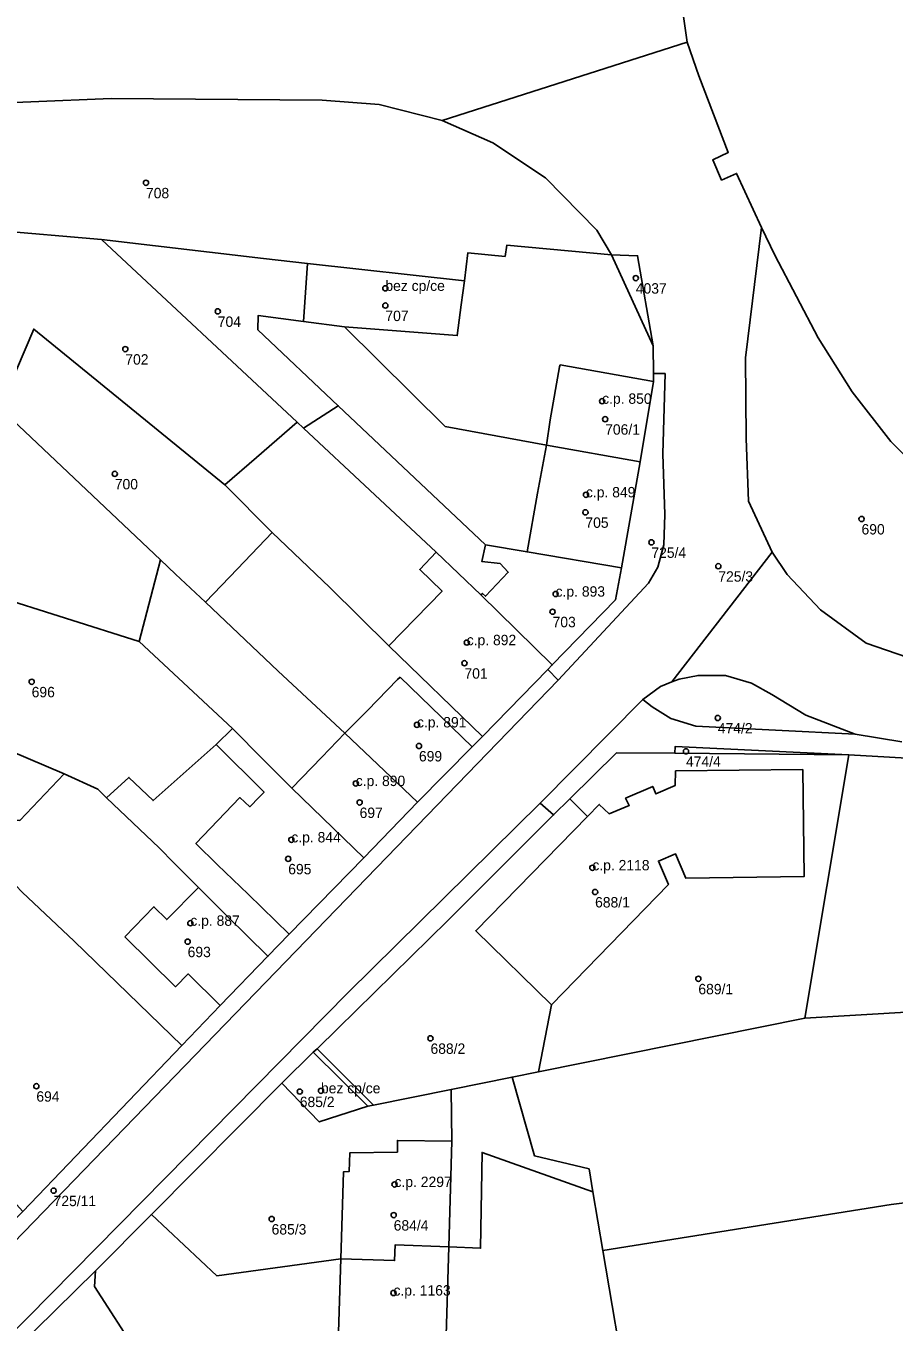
# Model space of a CAD drawing. Extents: x -878211 to -870363, y -1058464 to -1052522.
# Drawn here: x -874627.3 to -874543.8, y -1056425.6 to -1056300.9 of the extents above; entities that cross this region are included whole.
import ezdxf

# ---------------------------------------------------------------- set-up
doc = ezdxf.new("R2010")
doc.units = 0
for name, color, linetype in [('Definiční body', 7, 'Continuous'), ('Polygon budovy', 7, 'Continuous'), ('Polygon parcely', 7, 'Continuous')]:
    doc.layers.add(name, color=color, linetype=linetype)

msp = doc.modelspace()

# ---------------------------------------------------------------- linework, layer by layer
at = {"layer": 'Definiční body'}
for centre in [(-874615.77, -1056315.99994), (-874568.63, -1056325.16994), (-874592.73, -1056326.14994), (-874592.73, -1056327.80994), (-874608.86, -1056328.36994), (-874617.76, -1056331.99994), (-874571.87, -1056337.00994), (-874571.58, -1056338.73994), (-874618.77, -1056343.99994), (-874573.43, -1056346.00994), (-874573.48, -1056347.69994), (-874546.91, -1056348.33994), (-874567.13, -1056350.58994), (-874560.69, -1056352.87994), (-874576.35, -1056355.55994), (-874576.64, -1056357.25994), (-874584.9, -1056360.22994), (-874585.12, -1056362.20994), (-874626.77, -1056363.99994), (-874560.74, -1056367.47994), (-874589.69, -1056368.13994), (-874589.5, -1056370.16994), (-874563.8, -1056370.68994), (-874595.58, -1056373.77994), (-874595.21, -1056375.60994), (-874601.78, -1056379.19994), (-874602.08, -1056381.02994), (-874572.81, -1056381.88994), (-874572.55, -1056384.21994), (-874611.5, -1056387.21994), (-874611.76, -1056388.99994), (-874562.61, -1056392.56994), (-874588.39, -1056398.29994), (-874626.32, -1056402.89994), (-874600.97, -1056403.41994), (-874598.93, -1056403.33994), (-874591.85, -1056412.34994), (-874624.66, -1056412.94994), (-874603.68, -1056415.67994), (-874591.93, -1056415.29994), (-874591.95, -1056422.78994)]:
    msp.add_circle(centre, 0.25, dxfattribs=at)
at = {"layer": 'Polygon budovy'}
for points in [[(-874600.61, -1056329.35), (-874596.68, -1056329.87), (-874585.82, -1056330.7), (-874585.43, -1056327.73), (-874585.13, -1056325.44), (-874600.21, -1056323.77)], [(-874575.92, -1056333.5), (-874575.96, -1056333.7), (-874576.86, -1056338.81), (-874577.23, -1056341.24), (-874568.21, -1056342.85), (-874566.92, -1056335.1)], [(-874578.08, -1056345.85), (-874579.09, -1056351.51), (-874570.02, -1056353.03), (-874568.21, -1056342.85), (-874577.23, -1056341.24)], [(-874570.57, -1056356.1), (-874570.02, -1056353.03), (-874579.09, -1056351.51), (-874583.1, -1056350.84), (-874583.44, -1056352.43), (-874581.7, -1056352.63), (-874580.91, -1056353.47), (-874583.11, -1056355.77), (-874583.39, -1056355.5), (-874583.54, -1056355.64), (-874576.68, -1056362.38)], [(-874592.39, -1056360.55), (-874583.39, -1056369.26), (-874577.11, -1056362.82), (-874576.68, -1056362.38), (-874583.54, -1056355.64), (-874587.83, -1056351.54), (-874589.42, -1056353.2), (-874587.27, -1056355.27)], [(-874591.31, -1056363.55), (-874591.55, -1056363.78), (-874594.44, -1056366.75), (-874596.63, -1056368.95), (-874589.63, -1056375.57), (-874584.38, -1056370.26)], [(-874594.8, -1056380.92), (-874601.73, -1056374.23), (-874604.5, -1056371.46), (-874607.45, -1056368.5), (-874609, -1056370.04), (-874604.4, -1056374.61), (-874604.88, -1056375.11), (-874605.78, -1056376.02), (-874606.75, -1056375.14), (-874610.97, -1056379.54), (-874608.9, -1056381.6), (-874605.92, -1056384.44), (-874601.99, -1056388.27)], [(-874598.85, -1056371.26), (-874601.73, -1056374.23), (-874594.8, -1056380.92), (-874589.63, -1056375.57), (-874596.63, -1056368.95)], [(-874584.04, -1056387.95), (-874576.73, -1056395.06), (-874565.49, -1056383.5), (-874566.45, -1056381.25), (-874564.81, -1056380.56), (-874563.82, -1056382.88), (-874552.43, -1056382.73), (-874552.56, -1056372.44), (-874564.81, -1056372.58), (-874564.83, -1056373.96), (-874566.7, -1056374.79), (-874567, -1056374.06), (-874569.62, -1056375.2), (-874569.27, -1056375.89), (-874571.18, -1056376.7), (-874572.15, -1056375.8), (-874573.28, -1056376.95)], [(-874617.8, -1056388.54), (-874612.93, -1056393.33), (-874611.71, -1056392.1), (-874608.63, -1056395.13), (-874604.04, -1056390.4), (-874607.99, -1056386.5), (-874610.71, -1056383.8), (-874613.77, -1056386.88), (-874615.01, -1056385.64)], [(-874602.69, -1056402.62), (-874599.09, -1056406.34), (-874594.43, -1056404.83), (-874599.67, -1056399.64)], [(-874596.75, -1056411.13), (-874597.02, -1056419.51), (-874591.85, -1056419.68), (-874591.8, -1056418.17), (-874586.64, -1056418.34), (-874586.34, -1056408.2), (-874591.57, -1056408.12), (-874591.58, -1056409.24), (-874596.15, -1056409.31), (-874596.22, -1056411.11)], [(-874586.92, -1056427.91), (-874586.64, -1056418.34), (-874591.8, -1056418.17), (-874591.85, -1056419.68), (-874597.02, -1056419.51), (-874597.28, -1056427.58), (-874596.8, -1056427.63), (-874596.8, -1056431.5), (-874588.16, -1056431.92), (-874587.55, -1056431.96), (-874587.47, -1056427.91)]]:
    msp.add_lwpolyline(points, close=True, dxfattribs=at)
at = {"layer": 'Polygon parcely'}
for points in [[(-874680.13, -1056306.95), (-874668.48, -1056306.3), (-874658.74, -1056306.11), (-874647.74, -1056306.28), (-874639.68, -1056306.57), (-874634.55, -1056306.42), (-874634.61, -1056308.52), (-874619.11, -1056307.9), (-874598.82, -1056308.06), (-874593.33, -1056308.46), (-874587.28, -1056310.02), (-874563.7, -1056302.47), (-874564.67, -1056295.46), (-874565.68, -1056292.14), (-874573.3, -1056294.03), (-874588.19, -1056295.83), (-874618.11, -1056299.35), (-874618.18, -1056298.78), (-874635.16, -1056298.67), (-874650.22, -1056298.54), (-874650.2, -1056299.73), (-874665.6, -1056299.74), (-874676.84, -1056300.28)], [(-874564.67, -1056295.46), (-874563.7, -1056302.47), (-874562.58, -1056305.72), (-874559.74, -1056313.1), (-874561.22, -1056313.78), (-874560.38, -1056315.74), (-874558.93, -1056315.1), (-874556.55, -1056320.31), (-874555.24, -1056322.96), (-874551.07, -1056330.9), (-874547.81, -1056336.11), (-874544.09, -1056340.87), (-874539.67, -1056345.3)], [(-874635.99, -1056434.09), (-874596.3, -1056393.88), (-874577.85, -1056375.68), (-874567.96, -1056365.69), (-874566.25, -1056364.46), (-874565.16, -1056363.99), (-874555.5, -1056351.54), (-874557.77, -1056346.63), (-874558, -1056340.59), (-874558.06, -1056332.83), (-874556.55, -1056320.31), (-874558.93, -1056315.1), (-874560.38, -1056315.74), (-874561.22, -1056313.78), (-874559.74, -1056313.1), (-874562.58, -1056305.72), (-874563.7, -1056302.47), (-874587.28, -1056310.02), (-874582.38, -1056312.17), (-874577.32, -1056315.52), (-874572.37, -1056320.56), (-874570.96, -1056322.94), (-874568.46, -1056323.02), (-874566.96, -1056331.69), (-874566.93, -1056334.34), (-874565.81, -1056334.36), (-874566.03, -1056342.08), (-874565.84, -1056347.9), (-874565.93, -1056350.84), (-874566.5, -1056352.96), (-874567.41, -1056354.51), (-874576.09, -1056363.83), (-874637.28, -1056426.98)], [(-874630.52, -1056320.57), (-874620.05, -1056321.46), (-874604.47, -1056323.27), (-874600.21, -1056323.77), (-874585.13, -1056325.44), (-874584.8, -1056322.75), (-874581.21, -1056323.08), (-874581.05, -1056322.01), (-874570.96, -1056322.94), (-874572.37, -1056320.56), (-874577.32, -1056315.52), (-874582.38, -1056312.17), (-874587.28, -1056310.02), (-874593.33, -1056308.46), (-874598.82, -1056308.06), (-874619.11, -1056307.9), (-874634.61, -1056308.52)], [(-874541.52, -1056361.97), (-874546.46, -1056360.29), (-874550.87, -1056357.09), (-874554.07, -1056353.69), (-874555.5, -1056351.54), (-874565.16, -1056363.99), (-874564.46, -1056363.76), (-874562.64, -1056363.38), (-874560.01, -1056363.4), (-874557.5, -1056364.14), (-874555.53, -1056365.21), (-874552.26, -1056367.22), (-874547.51, -1056369.04), (-874543.04, -1056369.79)], [(-874637.28, -1056426.98), (-874576.09, -1056363.83), (-874577.11, -1056362.82), (-874583.39, -1056369.26), (-874584.38, -1056370.26), (-874589.63, -1056375.57), (-874594.8, -1056380.92), (-874601.99, -1056388.27), (-874604.04, -1056390.4), (-874608.63, -1056395.13), (-874612.31, -1056398.97), (-874627.63, -1056414.96), (-874630.17, -1056417.49), (-874636.41, -1056423.72), (-874645.88, -1056431.25)], [(-874543.04, -1056369.79), (-874547.51, -1056369.04), (-874562.87, -1056368.27), (-874565.25, -1056367.54), (-874567.05, -1056366.42), (-874567.96, -1056365.69), (-874577.85, -1056375.68), (-874576.54, -1056376.81), (-874574.99, -1056375.27), (-874570.48, -1056370.84), (-874564.86, -1056370.88), (-874564.84, -1056370.21), (-874548.14, -1056371.01), (-874516.29, -1056372.85)], [(-874671.18, -1056450.63), (-874653.34, -1056444.21), (-874650.6, -1056443.14), (-874645.72, -1056445.3), (-874620.62, -1056420.65), (-874615.24, -1056415.24), (-874602.69, -1056402.62), (-874599.67, -1056399.64), (-874599.31, -1056399.32), (-874597.3, -1056397.35), (-874586.71, -1056386.96), (-874576.54, -1056376.81), (-874577.85, -1056375.68), (-874596.3, -1056393.88), (-874635.99, -1056434.09), (-874637.85, -1056435.67), (-874640.47, -1056437.51), (-874643.52, -1056439.22), (-874649.14, -1056441.92), (-874658.33, -1056444.65), (-874665.5, -1056446.52), (-874670.55, -1056448.41)]]:
    msp.add_lwpolyline(points, dxfattribs=at)
for points in [[(-874636.56, -1056326.33), (-874640.51, -1056325.68), (-874639.47, -1056319.39), (-874640.17, -1056319.3), (-874647.02, -1056351.79), (-874637.74, -1056353.38), (-874616.44, -1056360.12), (-874614.38, -1056352.26), (-874629.83, -1056337.67), (-874633.4, -1056334.47), (-874630.52, -1056320.57), (-874635.53, -1056320)], [(-874601.23, -1056339.03), (-874620.05, -1056321.46), (-874630.52, -1056320.57), (-874633.4, -1056334.47), (-874629.83, -1056337.67), (-874626.57, -1056330.07), (-874608.19, -1056345.04), (-874605.14, -1056342.41)], [(-874544.09, -1056340.87), (-874547.81, -1056336.11), (-874551.07, -1056330.9), (-874555.24, -1056322.96), (-874556.55, -1056320.31), (-874558.06, -1056332.83), (-874558, -1056340.59), (-874557.77, -1056346.63), (-874555.5, -1056351.54), (-874554.07, -1056353.69), (-874550.87, -1056357.09), (-874546.46, -1056360.29), (-874541.52, -1056361.97), (-874533.36, -1056363.05), (-874528.54, -1056363.05), (-874520.8, -1056363.05), (-874517.72, -1056363.05), (-874516.65, -1056359.69), (-874516.14, -1056358.09), (-874524.65, -1056354.98), (-874530.08, -1056352.4), (-874535.19, -1056348.99), (-874539.67, -1056345.3)], [(-874600.61, -1056329.35), (-874600.21, -1056323.77), (-874604.47, -1056323.27), (-874620.05, -1056321.46), (-874601.23, -1056339.03), (-874600.62, -1056339.6), (-874597.27, -1056337.45), (-874604.99, -1056330.15), (-874604.97, -1056328.75)], [(-874566.92, -1056335.1), (-874566.93, -1056334.34), (-874566.96, -1056331.69), (-874570.96, -1056322.94), (-874581.05, -1056322.01), (-874581.21, -1056323.08), (-874584.8, -1056322.75), (-874585.13, -1056325.44), (-874585.43, -1056327.73), (-874585.82, -1056330.7), (-874596.68, -1056329.87), (-874586.98, -1056339.44), (-874577.23, -1056341.24), (-874568.21, -1056342.85)], [(-874585.13, -1056325.44), (-874600.21, -1056323.77), (-874600.61, -1056329.35), (-874596.68, -1056329.87), (-874585.82, -1056330.7), (-874585.43, -1056327.73)], [(-874570.96, -1056322.94), (-874566.96, -1056331.69), (-874568.46, -1056323.02)], [(-874568.21, -1056342.85), (-874577.23, -1056341.24), (-874586.98, -1056339.44), (-874596.68, -1056329.87), (-874600.61, -1056329.35), (-874604.97, -1056328.75), (-874604.99, -1056330.15), (-874597.27, -1056337.45), (-874583.1, -1056350.84), (-874579.09, -1056351.51), (-874570.02, -1056353.03)], [(-874608.19, -1056345.04), (-874626.57, -1056330.07), (-874629.83, -1056337.67), (-874614.38, -1056352.26), (-874612.92, -1056353.64), (-874610.04, -1056356.35), (-874606.96, -1056353.12), (-874603.63, -1056349.63)], [(-874576.09, -1056363.83), (-874567.41, -1056354.51), (-874566.5, -1056352.96), (-874565.93, -1056350.84), (-874565.84, -1056347.9), (-874566.03, -1056342.08), (-874565.81, -1056334.36), (-874566.93, -1056334.34), (-874566.92, -1056335.1), (-874568.21, -1056342.85), (-874570.02, -1056353.03), (-874570.57, -1056356.1), (-874576.68, -1056362.38), (-874577.11, -1056362.82)], [(-874570.57, -1056356.1), (-874570.02, -1056353.03), (-874579.09, -1056351.51), (-874583.1, -1056350.84), (-874597.27, -1056337.45), (-874600.62, -1056339.6), (-874587.83, -1056351.54), (-874583.54, -1056355.64), (-874576.68, -1056362.38)], [(-874583.39, -1056369.26), (-874577.11, -1056362.82), (-874576.68, -1056362.38), (-874583.54, -1056355.64), (-874587.83, -1056351.54), (-874600.62, -1056339.6), (-874601.23, -1056339.03), (-874605.14, -1056342.41), (-874608.19, -1056345.04), (-874603.63, -1056349.63), (-874598.08, -1056354.93), (-874592.39, -1056360.55)], [(-874584.38, -1056370.26), (-874583.39, -1056369.26), (-874592.39, -1056360.55), (-874598.08, -1056354.93), (-874603.63, -1056349.63), (-874606.96, -1056353.12), (-874610.04, -1056356.35), (-874603.04, -1056362.97), (-874596.63, -1056368.95), (-874589.63, -1056375.57)], [(-874589.63, -1056375.57), (-874596.63, -1056368.95), (-874603.04, -1056362.97), (-874610.04, -1056356.35), (-874612.92, -1056353.64), (-874614.38, -1056352.26), (-874616.44, -1056360.12), (-874607.45, -1056368.5), (-874604.5, -1056371.46), (-874601.73, -1056374.23), (-874594.8, -1056380.92)], [(-874616.44, -1056360.12), (-874637.74, -1056353.38), (-874638.97, -1056357.91), (-874640.78, -1056365.59), (-874623.65, -1056372.86), (-874620.41, -1056374.33), (-874619.57, -1056375.15), (-874617.41, -1056373.2), (-874615.09, -1056375.43), (-874609, -1056370.04), (-874607.45, -1056368.5)], [(-874547.51, -1056369.04), (-874552.26, -1056367.22), (-874555.53, -1056365.21), (-874557.5, -1056364.14), (-874560.01, -1056363.4), (-874562.64, -1056363.38), (-874564.46, -1056363.76), (-874565.16, -1056363.99), (-874566.25, -1056364.46), (-874567.96, -1056365.69), (-874567.05, -1056366.42), (-874565.25, -1056367.54), (-874562.87, -1056368.27)], [(-874612.31, -1056398.97), (-874622.68, -1056388.94), (-874627.69, -1056384.22), (-874628.3, -1056383.59), (-874632, -1056380.04), (-874629.36, -1056377.31), (-874627.9, -1056377.33), (-874623.65, -1056372.86), (-874640.78, -1056365.59), (-874641.59, -1056369.03), (-874644.17, -1056380.32), (-874646, -1056388.37), (-874646.91, -1056392.27), (-874647.07, -1056392.98), (-874644.81, -1056392.82), (-874634.78, -1056392.46), (-874635.26, -1056395.42), (-874639.07, -1056403.74), (-874635.37, -1056406.43), (-874627.63, -1056414.96)], [(-874601.99, -1056388.27), (-874594.8, -1056380.92), (-874601.73, -1056374.23), (-874604.5, -1056371.46), (-874607.45, -1056368.5), (-874609, -1056370.04), (-874615.09, -1056375.43), (-874617.41, -1056373.2), (-874619.57, -1056375.15), (-874614.5, -1056379.96), (-874613.07, -1056381.44), (-874610.71, -1056383.8), (-874607.99, -1056386.5), (-874604.04, -1056390.4)], [(-874576.73, -1056395.06), (-874577.98, -1056401.51), (-874552.37, -1056396.35), (-874548.14, -1056371.01), (-874564.86, -1056370.88), (-874570.48, -1056370.84), (-874574.99, -1056375.27), (-874573.28, -1056376.95), (-874572.15, -1056375.8), (-874571.18, -1056376.7), (-874569.27, -1056375.89), (-874569.62, -1056375.2), (-874567, -1056374.06), (-874566.7, -1056374.79), (-874564.83, -1056373.96), (-874564.81, -1056372.58), (-874552.56, -1056372.44), (-874552.43, -1056382.73), (-874563.82, -1056382.88), (-874564.81, -1056380.56), (-874566.45, -1056381.25), (-874565.49, -1056383.5)], [(-874564.86, -1056370.88), (-874548.14, -1056371.01), (-874564.84, -1056370.21)], [(-874548.14, -1056371.01), (-874552.37, -1056396.35), (-874510.08, -1056393.87), (-874504.25, -1056392.93), (-874500.89, -1056392.21), (-874497.18, -1056388.52), (-874496.42, -1056387.17), (-874495.04, -1056376.59), (-874516.29, -1056372.85)], [(-874573.28, -1056376.95), (-874584.04, -1056387.95), (-874576.73, -1056395.06), (-874565.49, -1056383.5), (-874566.45, -1056381.25), (-874564.81, -1056380.56), (-874563.82, -1056382.88), (-874552.43, -1056382.73), (-874552.56, -1056372.44), (-874564.81, -1056372.58), (-874564.83, -1056373.96), (-874566.7, -1056374.79), (-874567, -1056374.06), (-874569.62, -1056375.2), (-874569.27, -1056375.89), (-874571.18, -1056376.7), (-874572.15, -1056375.8)], [(-874604.04, -1056390.4), (-874607.99, -1056386.5), (-874610.71, -1056383.8), (-874613.07, -1056381.44), (-874614.5, -1056379.96), (-874619.57, -1056375.15), (-874620.41, -1056374.33), (-874623.65, -1056372.86), (-874627.9, -1056377.33), (-874629.36, -1056377.31), (-874632, -1056380.04), (-874628.3, -1056383.59), (-874627.69, -1056384.22), (-874622.68, -1056388.94), (-874612.31, -1056398.97), (-874608.63, -1056395.13)], [(-874586.71, -1056386.96), (-874597.3, -1056397.35), (-874599.31, -1056399.32), (-874593.88, -1056404.72), (-874586.39, -1056403.21), (-874580.53, -1056402.03), (-874577.98, -1056401.51), (-874576.73, -1056395.06), (-874584.04, -1056387.95), (-874573.28, -1056376.95), (-874574.99, -1056375.27), (-874576.54, -1056376.81)], [(-874480.73, -1056416.32), (-874464.13, -1056411.06), (-874439.22, -1056401.77), (-874435.23, -1056399.98), (-874432.58, -1056397.69), (-874438.32, -1056392.45), (-874461.59, -1056384.57), (-874473.8, -1056381.18), (-874495.04, -1056376.59), (-874496.42, -1056387.17), (-874497.18, -1056388.52), (-874500.89, -1056392.21), (-874504.25, -1056392.93), (-874510.08, -1056393.87), (-874552.37, -1056396.35), (-874577.98, -1056401.51), (-874580.53, -1056402.03), (-874578.38, -1056409.61), (-874573.13, -1056410.85), (-874572.76, -1056413.05), (-874571.8, -1056418.71), (-874544.06, -1056414.29), (-874506.28, -1056409.52), (-874484.53, -1056404.72)], [(-874599.31, -1056399.32), (-874599.67, -1056399.64), (-874602.69, -1056402.62), (-874599.09, -1056406.34), (-874594.43, -1056404.83), (-874593.88, -1056404.72)], [(-874596.75, -1056411.13), (-874597.02, -1056419.51), (-874591.85, -1056419.68), (-874591.8, -1056418.17), (-874586.64, -1056418.34), (-874583.57, -1056418.49), (-874583.42, -1056409.27), (-874572.76, -1056413.05), (-874573.13, -1056410.85), (-874578.38, -1056409.61), (-874580.53, -1056402.03), (-874586.39, -1056403.21), (-874586.34, -1056408.2), (-874591.57, -1056408.12), (-874591.58, -1056409.24), (-874596.15, -1056409.31), (-874596.22, -1056411.11)], [(-874602.69, -1056402.62), (-874615.24, -1056415.24), (-874608.94, -1056421.13), (-874597.02, -1056419.51), (-874596.75, -1056411.13), (-874596.22, -1056411.11), (-874596.15, -1056409.31), (-874591.58, -1056409.24), (-874591.57, -1056408.12), (-874586.34, -1056408.2), (-874586.39, -1056403.21), (-874593.88, -1056404.72), (-874594.43, -1056404.83), (-874599.09, -1056406.34)], [(-874506.63, -1056424.46), (-874505.5, -1056424.13), (-874490.03, -1056419.45), (-874482.07, -1056416.75), (-874480.73, -1056416.32), (-874484.53, -1056404.72), (-874506.28, -1056409.52), (-874544.06, -1056414.29), (-874571.8, -1056418.71), (-874569.39, -1056432.89), (-874561.56, -1056432.43), (-874554.89, -1056431.78), (-874547.93, -1056431.29), (-874538.64, -1056430.41), (-874535.46, -1056430.33), (-874523.03, -1056429.03), (-874509.91, -1056425.43)], [(-874583.57, -1056418.49), (-874586.64, -1056418.34), (-874591.8, -1056418.17), (-874591.85, -1056419.68), (-874597.02, -1056419.51), (-874597.28, -1056427.58), (-874596.8, -1056427.63), (-874596.8, -1056431.5), (-874588.16, -1056431.92), (-874587.55, -1056431.96), (-874575.47, -1056432.55), (-874573.16, -1056432.7), (-874570.27, -1056432.92), (-874569.39, -1056432.89), (-874571.8, -1056418.71), (-874572.76, -1056413.05), (-874583.42, -1056409.27)], [(-874615.24, -1056415.24), (-874620.62, -1056420.65), (-874620.73, -1056422.16), (-874616.6, -1056428.57), (-874614.09, -1056430.86), (-874596.8, -1056431.5), (-874596.8, -1056427.63), (-874597.28, -1056427.58), (-874597.02, -1056419.51), (-874608.94, -1056421.13)], [(-874620.62, -1056420.65), (-874645.72, -1056445.3), (-874606.46, -1056464.04), (-874595.59, -1056464.97), (-874595.05, -1056462.65), (-874588.96, -1056435.96), (-874588.16, -1056431.92), (-874596.8, -1056431.5), (-874614.09, -1056430.86), (-874616.6, -1056428.57), (-874620.73, -1056422.16)]]:
    msp.add_lwpolyline(points, close=True, dxfattribs=at)

# ---------------------------------------------------------------- texts
at = {"layer": 'Definiční body'}
for s, p in [('708', (-874615.77, -1056317.489)), ('bez cp/ce', (-874592.73, -1056326.399)), ('4037', (-874568.63, -1056326.659)), ('704', (-874608.86, -1056329.859)), ('707', (-874592.73, -1056329.299)), ('702', (-874617.76, -1056333.489)), ('c.p. 850', (-874571.87, -1056337.26)), ('706/1', (-874571.58, -1056340.229)), ('700', (-874618.77, -1056345.489)), ('c.p. 849', (-874573.43, -1056346.26)), ('705', (-874573.48, -1056349.189)), ('690', (-874546.91, -1056349.829)), ('725/4', (-874567.13, -1056352.079)), ('725/3', (-874560.69, -1056354.369)), ('c.p. 893', (-874576.35, -1056355.81)), ('703', (-874576.64, -1056358.749)), ('c.p. 892', (-874584.9, -1056360.48)), ('701', (-874585.12, -1056363.699)), ('696', (-874626.77, -1056365.489)), ('c.p. 891', (-874589.69, -1056368.389)), ('474/2', (-874560.74, -1056368.969)), ('699', (-874589.5, -1056371.659)), ('474/4', (-874563.8, -1056372.179)), ('c.p. 890', (-874595.58, -1056374.03)), ('697', (-874595.21, -1056377.099)), ('c.p. 844', (-874601.78, -1056379.45)), ('c.p. 2118', (-874572.81, -1056382.139)), ('695', (-874602.08, -1056382.519)), ('688/1', (-874572.55, -1056385.709)), ('c.p. 887', (-874611.5, -1056387.47)), ('693', (-874611.76, -1056390.489)), ('689/1', (-874562.61, -1056394.059)), ('688/2', (-874588.39, -1056399.789)), ('694', (-874626.32, -1056404.389)), ('bez cp/ce', (-874598.93, -1056403.59)), ('685/2', (-874600.97, -1056404.909)), ('c.p. 2297', (-874591.85, -1056412.6)), ('725/11', (-874624.66, -1056414.439)), ('685/3', (-874603.68, -1056417.169)), ('684/4', (-874591.93, -1056416.789)), ('c.p. 1163', (-874591.95, -1056423.04))]:
    msp.add_text(s, height=0.999996, dxfattribs=at).set_placement(p)

doc.saveas('drawing.dxf')
